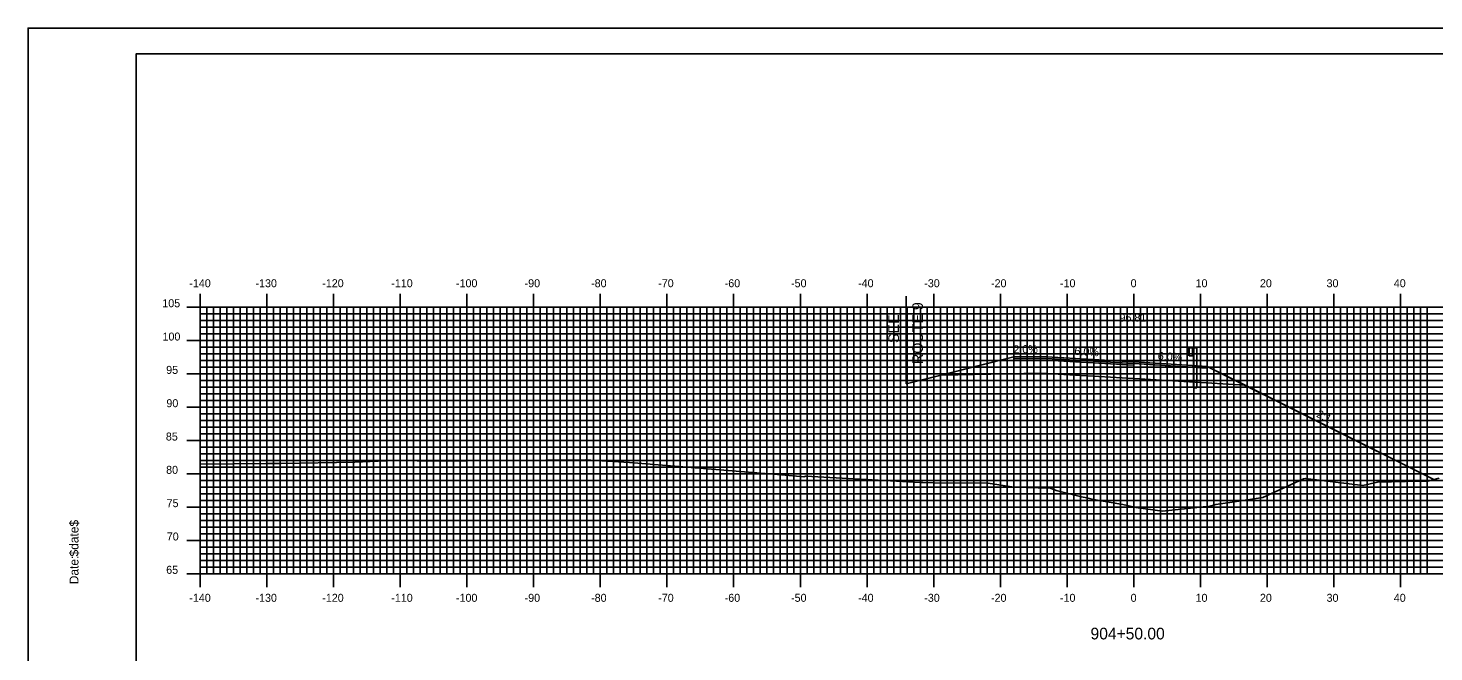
# Model space of a CAD drawing. Extents: x 857110 to 857453, y 364765 to 364985.
# Drawn here: x 857110 to 857320.8, y 364891.6 to 364985.2 of the extents above; entities that cross this region are included whole.
import ezdxf

# ---------------------------------------------------------------- set-up
doc = ezdxf.new("R2010")
doc.units = 0
for name, color, linetype in [('ANNOTATION', 7, 'Continuous'), ('BORDER', 7, 'Continuous'), ('D_Guardrail_Beam_Rt', 7, 'Continuous'), ('D_Roadway_Centerline', 7, 'Continuous'), ('D_Roadway_Centerline_Text', 7, 'Continuous'), ('D_Roadway_Edge_Shoulder', 7, 'Continuous'), ('D_Roadway_Edge_TW', 7, 'Continuous'), ('D_Roadway_Pavement', 7, 'Continuous'), ('D_Roadway_SlopeLines', 7, 'Continuous'), ('D_Roadway_SubGrade', 7, 'Continuous'), ('H_V ANNOTATION', 7, 'Continuous'), ('MAJOR', 7, 'Continuous'), ('MINOR', 7, 'Continuous'), ('PLOT BOUNDARY', 7, 'Continuous'), ('S_Roadway_Centerline', 7, 'Continuous')]:
    doc.layers.add(name, color=color, linetype=linetype)

msp = doc.modelspace()

# ---------------------------------------------------------------- linework, layer by layer
at = {"layer": 'BORDER'}
msp.add_lwpolyline([(857126.19, 364771.3), (857446.19, 364771.3), (857446.19, 364981.3), (857126.19, 364981.3)], close=True, dxfattribs=at)
at = {"layer": 'D_Guardrail_Beam_Rt'}
for p, q in [((857283.98, 364937.09), (857283.83, 364936.99)), ((857283.83, 364936.84), (857284.03, 364936.71)), ((857284.03, 364936.51), (857283.83, 364936.37)), ((857283.83, 364936.23), (857283.98, 364936.13)), ((857284.07, 364937.11), (857283.99, 364937.09)), ((857283.99, 364936.12), (857284.07, 364936.11)), ((857284.06, 364936.64), (857284.06, 364936.57)), ((857284.07, 364937.19), (857284.75, 364937.19)), ((857284.07, 364936.02), (857284.07, 364937.19)), ((857284.59, 364937.19), (857284.59, 364936.02)), ((857284.69, 364937.19), (857284.69, 364936.02)), ((857284.75, 364937.19), (857285.22, 364937.19)), ((857284.75, 364937.19), (857284.75, 364936.02)), ((857285.22, 364937.19), (857285.22, 364931.19)), ((857284.75, 364936.02), (857284.07, 364936.02)), ((857284.73, 364931.19), (857284.73, 364936.02)), ((857284.73, 364931.19), (857285.22, 364931.19))]:
    msp.add_line(p, q, dxfattribs=at)
for centre, major_axis, start_param, end_param in [((857283.88, 364936.91), (-0.0877, 0), 5.323254, 7.243116), ((857283.88, 364936.3), (-0.0877, 0), 5.323254, 7.243116), ((857284, 364937.05), (-0.0417, 0), 4.907132, 5.323254), ((857284, 364936.16), (-0.0417, 0), 0.959931, 1.376053), ((857283.98, 364936.64), (0.0789, 0), 0, 0.959931), ((857283.98, 364936.57), (0.0789, 0), 5.323254, 6.283185)]:
    msp.add_ellipse(centre, major_axis=major_axis, ratio=0.995501, start_param=start_param, end_param=end_param, dxfattribs=at)
at = {"layer": 'D_Roadway_Centerline'}
msp.add_lwpolyline([(857246.92, 364933.13), (857257.79, 364935.85), (857261.79, 364935.93), (857275.79, 364935.09), (857283.79, 364934.61), (857286.79, 364934.43), (857292.48, 364931.59), (857320.76, 364917.44)], dxfattribs=at)
at = {"layer": 'D_Roadway_Edge_Shoulder'}
for points in [[(857261.79, 364935.93), (857257.79, 364935.85), (857257.79, 364935.6), (857261.79, 364935.68)], [(857275.79, 364935.09), (857283.79, 364934.61), (857283.79, 364934.61), (857286.79, 364934.43), (857286.79, 364934.18), (857275.79, 364934.84)]]:
    msp.add_lwpolyline(points, close=True, dxfattribs=at)
at = {"layer": 'D_Roadway_Edge_TW'}
msp.add_lwpolyline([(857261.79, 364935.93), (857275.79, 364935.09), (857275.79, 364934.84), (857261.79, 364935.68)], close=True, dxfattribs=at)
at = {"layer": 'D_Roadway_Pavement'}
for points in [[(857261.79, 364935.68), (857257.79, 364935.6), (857257.79, 364935.35), (857261.79, 364935.43)], [(857261.79, 364935.68), (857275.79, 364934.84), (857275.79, 364934.59), (857261.79, 364935.43)]]:
    msp.add_lwpolyline(points, close=True, dxfattribs=at)
msp.add_lwpolyline([(857275.79, 364934.84), (857275.79, 364934.59)], dxfattribs=at)
msp.add_lwpolyline([(857275.79, 364934.84), (857275.79, 364934.59)], dxfattribs=at)
msp.add_lwpolyline([(857275.79, 364934.84), (857275.79, 364934.59)], dxfattribs=at)
at = {"layer": 'D_Roadway_SlopeLines'}
for points in [[(857286.79, 364934.43), (857320.76, 364917.44)], [(857241.65, 364931.81), (857246.92, 364933.13)]]:
    msp.add_lwpolyline(points, dxfattribs=at)
at = {"layer": 'D_Roadway_SubGrade'}
msp.add_line((857241.65, 364944.95), (857241.65, 364931.81), dxfattribs=at)
for points in [[(857261.79, 364935.43), (857257.79, 364935.35), (857257.79, 364935.6), (857257.79, 364935.85), (857246.92, 364933.13), (857261.79, 364933.43)], [(857261.79, 364935.43), (857275.79, 364934.59), (857275.79, 364932.59), (857261.79, 364933.43)], [(857275.79, 364934.59), (857275.79, 364934.84), (857286.79, 364934.18), (857286.79, 364934.43), (857292.48, 364931.59), (857275.79, 364932.59)]]:
    msp.add_lwpolyline(points, close=True, dxfattribs=at)
at = {"layer": 'MAJOR'}
for p, q in [((857135.79, 364945.31), (857135.79, 364943.3)), ((857145.79, 364945.31), (857145.79, 364943.3)), ((857155.79, 364945.31), (857155.79, 364943.3)), ((857165.79, 364945.31), (857165.79, 364943.3)), ((857175.79, 364945.31), (857175.79, 364943.3)), ((857185.79, 364945.31), (857185.79, 364943.3)), ((857195.79, 364945.31), (857195.79, 364943.3)), ((857205.79, 364945.31), (857205.79, 364943.3)), ((857215.79, 364945.31), (857215.79, 364943.3)), ((857225.79, 364945.31), (857225.79, 364943.3)), ((857235.79, 364945.31), (857235.79, 364943.3)), ((857245.79, 364945.31), (857245.79, 364943.3)), ((857255.79, 364945.31), (857255.79, 364943.3)), ((857265.79, 364945.31), (857265.79, 364943.3)), ((857275.79, 364945.31), (857275.79, 364943.3)), ((857285.79, 364945.31), (857285.79, 364943.3)), ((857295.79, 364945.31), (857295.79, 364943.3)), ((857305.79, 364945.31), (857305.79, 364943.3)), ((857315.79, 364945.31), (857315.79, 364943.3)), ((857133.79, 364943.3), (857135.79, 364943.3)), ((857135.79, 364943.3), (857415.79, 364943.3)), ((857135.79, 364903.3), (857135.79, 364943.3)), ((857135.79, 364903.3), (857135.79, 364943.3)), ((857135.79, 364943.3), (857415.79, 364943.3)), ((857145.79, 364903.3), (857145.79, 364943.3)), ((857155.79, 364903.3), (857155.79, 364943.3)), ((857165.79, 364903.3), (857165.79, 364943.3)), ((857175.79, 364903.3), (857175.79, 364943.3)), ((857185.79, 364903.3), (857185.79, 364943.3)), ((857195.79, 364903.3), (857195.79, 364943.3)), ((857205.79, 364903.3), (857205.79, 364943.3)), ((857215.79, 364903.3), (857215.79, 364943.3)), ((857225.79, 364903.3), (857225.79, 364943.3)), ((857235.79, 364903.3), (857235.79, 364943.3)), ((857245.79, 364903.3), (857245.79, 364943.3)), ((857255.79, 364903.3), (857255.79, 364943.3)), ((857265.79, 364903.3), (857265.79, 364943.3)), ((857275.79, 364903.3), (857275.79, 364943.3)), ((857285.79, 364903.3), (857285.79, 364943.3)), ((857295.79, 364903.3), (857295.79, 364943.3)), ((857305.79, 364903.3), (857305.79, 364943.3)), ((857315.79, 364903.3), (857315.79, 364943.3)), ((857133.79, 364938.3), (857135.79, 364938.3)), ((857135.79, 364938.3), (857415.79, 364938.3)), ((857133.79, 364933.3), (857135.79, 364933.3)), ((857135.79, 364933.3), (857415.79, 364933.3)), ((857133.79, 364928.3), (857135.79, 364928.3)), ((857135.79, 364928.3), (857415.79, 364928.3)), ((857133.79, 364923.3), (857135.79, 364923.3)), ((857135.79, 364923.3), (857415.79, 364923.3)), ((857133.79, 364918.3), (857135.79, 364918.3)), ((857135.79, 364918.3), (857415.79, 364918.3)), ((857133.79, 364913.3), (857135.79, 364913.3)), ((857135.79, 364913.3), (857415.79, 364913.3)), ((857133.79, 364908.3), (857135.79, 364908.3)), ((857135.79, 364908.3), (857415.79, 364908.3)), ((857133.79, 364903.3), (857135.79, 364903.3)), ((857135.79, 364903.3), (857415.79, 364903.3)), ((857135.79, 364903.3), (857415.79, 364903.3)), ((857135.79, 364901.3), (857135.79, 364903.3)), ((857145.79, 364901.3), (857145.79, 364903.3)), ((857155.79, 364901.3), (857155.79, 364903.3)), ((857165.79, 364901.3), (857165.79, 364903.3)), ((857175.79, 364901.3), (857175.79, 364903.3)), ((857185.79, 364901.3), (857185.79, 364903.3)), ((857195.79, 364901.3), (857195.79, 364903.3)), ((857205.79, 364901.3), (857205.79, 364903.3)), ((857215.79, 364901.3), (857215.79, 364903.3)), ((857225.79, 364901.3), (857225.79, 364903.3)), ((857235.79, 364901.3), (857235.79, 364903.3)), ((857245.79, 364901.3), (857245.79, 364903.3)), ((857255.79, 364901.3), (857255.79, 364903.3)), ((857265.79, 364901.3), (857265.79, 364903.3)), ((857275.79, 364901.3), (857275.79, 364903.3)), ((857285.79, 364901.3), (857285.79, 364903.3)), ((857295.79, 364901.3), (857295.79, 364903.3)), ((857305.79, 364901.3), (857305.79, 364903.3)), ((857315.79, 364901.3), (857315.79, 364903.3))]:
    msp.add_line(p, q, dxfattribs=at)
at = {"layer": 'MINOR'}
for p, q in [((857136.79, 364903.3), (857136.79, 364943.3)), ((857137.79, 364903.3), (857137.79, 364943.3)), ((857138.79, 364903.3), (857138.79, 364943.3)), ((857139.79, 364903.3), (857139.79, 364943.3)), ((857140.79, 364903.3), (857140.79, 364943.3)), ((857141.79, 364903.3), (857141.79, 364943.3)), ((857142.79, 364903.3), (857142.79, 364943.3)), ((857143.79, 364903.3), (857143.79, 364943.3)), ((857144.79, 364903.3), (857144.79, 364943.3)), ((857146.79, 364903.3), (857146.79, 364943.3)), ((857147.79, 364903.3), (857147.79, 364943.3)), ((857148.79, 364903.3), (857148.79, 364943.3)), ((857149.79, 364903.3), (857149.79, 364943.3)), ((857150.79, 364903.3), (857150.79, 364943.3)), ((857151.79, 364903.3), (857151.79, 364943.3)), ((857152.79, 364903.3), (857152.79, 364943.3)), ((857153.79, 364903.3), (857153.79, 364943.3)), ((857154.79, 364903.3), (857154.79, 364943.3)), ((857156.79, 364903.3), (857156.79, 364943.3)), ((857157.79, 364903.3), (857157.79, 364943.3)), ((857158.79, 364903.3), (857158.79, 364943.3)), ((857159.79, 364903.3), (857159.79, 364943.3)), ((857160.79, 364903.3), (857160.79, 364943.3)), ((857161.79, 364903.3), (857161.79, 364943.3)), ((857162.79, 364903.3), (857162.79, 364943.3)), ((857163.79, 364903.3), (857163.79, 364943.3)), ((857164.79, 364903.3), (857164.79, 364943.3)), ((857166.79, 364903.3), (857166.79, 364943.3)), ((857167.79, 364903.3), (857167.79, 364943.3)), ((857168.79, 364903.3), (857168.79, 364943.3)), ((857169.79, 364903.3), (857169.79, 364943.3)), ((857170.79, 364903.3), (857170.79, 364943.3)), ((857171.79, 364903.3), (857171.79, 364943.3)), ((857172.79, 364903.3), (857172.79, 364943.3)), ((857173.79, 364903.3), (857173.79, 364943.3)), ((857174.79, 364903.3), (857174.79, 364943.3)), ((857176.79, 364903.3), (857176.79, 364943.3)), ((857177.79, 364903.3), (857177.79, 364943.3)), ((857178.79, 364903.3), (857178.79, 364943.3)), ((857179.79, 364903.3), (857179.79, 364943.3)), ((857180.79, 364903.3), (857180.79, 364943.3)), ((857181.79, 364903.3), (857181.79, 364943.3)), ((857182.79, 364903.3), (857182.79, 364943.3)), ((857183.79, 364903.3), (857183.79, 364943.3)), ((857184.79, 364903.3), (857184.79, 364943.3)), ((857186.79, 364903.3), (857186.79, 364943.3)), ((857187.79, 364903.3), (857187.79, 364943.3)), ((857188.79, 364903.3), (857188.79, 364943.3)), ((857189.79, 364903.3), (857189.79, 364943.3)), ((857190.79, 364903.3), (857190.79, 364943.3)), ((857191.79, 364903.3), (857191.79, 364943.3)), ((857192.79, 364903.3), (857192.79, 364943.3)), ((857193.79, 364903.3), (857193.79, 364943.3)), ((857194.79, 364903.3), (857194.79, 364943.3)), ((857196.79, 364903.3), (857196.79, 364943.3)), ((857197.79, 364903.3), (857197.79, 364943.3)), ((857198.79, 364903.3), (857198.79, 364943.3)), ((857199.79, 364903.3), (857199.79, 364943.3)), ((857200.79, 364903.3), (857200.79, 364943.3)), ((857201.79, 364903.3), (857201.79, 364943.3)), ((857202.79, 364903.3), (857202.79, 364943.3)), ((857203.79, 364903.3), (857203.79, 364943.3)), ((857204.79, 364903.3), (857204.79, 364943.3)), ((857206.79, 364903.3), (857206.79, 364943.3)), ((857207.79, 364903.3), (857207.79, 364943.3)), ((857208.79, 364903.3), (857208.79, 364943.3)), ((857209.79, 364903.3), (857209.79, 364943.3)), ((857210.79, 364903.3), (857210.79, 364943.3)), ((857211.79, 364903.3), (857211.79, 364943.3)), ((857212.79, 364903.3), (857212.79, 364943.3)), ((857213.79, 364903.3), (857213.79, 364943.3)), ((857214.79, 364903.3), (857214.79, 364943.3)), ((857216.79, 364903.3), (857216.79, 364943.3)), ((857217.79, 364903.3), (857217.79, 364943.3)), ((857218.79, 364903.3), (857218.79, 364943.3)), ((857219.79, 364903.3), (857219.79, 364943.3)), ((857220.79, 364903.3), (857220.79, 364943.3)), ((857221.79, 364903.3), (857221.79, 364943.3)), ((857222.79, 364903.3), (857222.79, 364943.3)), ((857223.79, 364903.3), (857223.79, 364943.3)), ((857224.79, 364903.3), (857224.79, 364943.3)), ((857226.79, 364903.3), (857226.79, 364943.3)), ((857227.79, 364903.3), (857227.79, 364943.3)), ((857228.79, 364903.3), (857228.79, 364943.3)), ((857229.79, 364903.3), (857229.79, 364943.3)), ((857230.79, 364903.3), (857230.79, 364943.3)), ((857231.79, 364903.3), (857231.79, 364943.3)), ((857232.79, 364903.3), (857232.79, 364943.3)), ((857233.79, 364903.3), (857233.79, 364943.3)), ((857234.79, 364903.3), (857234.79, 364943.3)), ((857236.79, 364903.3), (857236.79, 364943.3)), ((857237.79, 364903.3), (857237.79, 364943.3)), ((857238.79, 364903.3), (857238.79, 364943.3)), ((857239.79, 364903.3), (857239.79, 364943.3)), ((857240.79, 364903.3), (857240.79, 364943.3)), ((857241.79, 364903.3), (857241.79, 364943.3)), ((857242.79, 364903.3), (857242.79, 364943.3)), ((857243.79, 364903.3), (857243.79, 364943.3)), ((857244.79, 364903.3), (857244.79, 364943.3)), ((857246.79, 364903.3), (857246.79, 364943.3)), ((857247.79, 364903.3), (857247.79, 364943.3)), ((857248.79, 364903.3), (857248.79, 364943.3)), ((857249.79, 364903.3), (857249.79, 364943.3)), ((857250.79, 364903.3), (857250.79, 364943.3)), ((857251.79, 364903.3), (857251.79, 364943.3)), ((857252.79, 364903.3), (857252.79, 364943.3)), ((857253.79, 364903.3), (857253.79, 364943.3)), ((857254.79, 364903.3), (857254.79, 364943.3)), ((857256.79, 364903.3), (857256.79, 364943.3)), ((857257.79, 364903.3), (857257.79, 364943.3)), ((857258.79, 364903.3), (857258.79, 364943.3)), ((857259.79, 364903.3), (857259.79, 364943.3)), ((857260.79, 364903.3), (857260.79, 364943.3)), ((857261.79, 364903.3), (857261.79, 364943.3)), ((857262.79, 364903.3), (857262.79, 364943.3)), ((857263.79, 364903.3), (857263.79, 364943.3)), ((857264.79, 364903.3), (857264.79, 364943.3)), ((857266.79, 364903.3), (857266.79, 364943.3)), ((857267.79, 364903.3), (857267.79, 364943.3)), ((857268.79, 364903.3), (857268.79, 364943.3)), ((857269.79, 364903.3), (857269.79, 364943.3)), ((857270.79, 364903.3), (857270.79, 364943.3)), ((857271.79, 364903.3), (857271.79, 364943.3)), ((857272.79, 364903.3), (857272.79, 364943.3)), ((857273.79, 364903.3), (857273.79, 364943.3)), ((857274.79, 364903.3), (857274.79, 364943.3)), ((857276.79, 364903.3), (857276.79, 364943.3)), ((857277.79, 364903.3), (857277.79, 364943.3)), ((857278.79, 364903.3), (857278.79, 364943.3)), ((857279.79, 364903.3), (857279.79, 364943.3)), ((857280.79, 364903.3), (857280.79, 364943.3)), ((857281.79, 364903.3), (857281.79, 364943.3)), ((857282.79, 364903.3), (857282.79, 364943.3)), ((857283.79, 364903.3), (857283.79, 364943.3)), ((857284.79, 364903.3), (857284.79, 364943.3)), ((857286.79, 364903.3), (857286.79, 364943.3)), ((857287.79, 364903.3), (857287.79, 364943.3)), ((857288.79, 364903.3), (857288.79, 364943.3)), ((857289.79, 364903.3), (857289.79, 364943.3)), ((857290.79, 364903.3), (857290.79, 364943.3)), ((857291.79, 364903.3), (857291.79, 364943.3)), ((857292.79, 364903.3), (857292.79, 364943.3)), ((857293.79, 364903.3), (857293.79, 364943.3)), ((857294.79, 364903.3), (857294.79, 364943.3)), ((857296.79, 364903.3), (857296.79, 364943.3)), ((857297.79, 364903.3), (857297.79, 364943.3)), ((857298.79, 364903.3), (857298.79, 364943.3)), ((857299.79, 364903.3), (857299.79, 364943.3)), ((857300.79, 364903.3), (857300.79, 364943.3)), ((857301.79, 364903.3), (857301.79, 364943.3)), ((857302.79, 364903.3), (857302.79, 364943.3)), ((857303.79, 364903.3), (857303.79, 364943.3)), ((857304.79, 364903.3), (857304.79, 364943.3)), ((857306.79, 364903.3), (857306.79, 364943.3)), ((857307.79, 364903.3), (857307.79, 364943.3)), ((857308.79, 364903.3), (857308.79, 364943.3)), ((857309.79, 364903.3), (857309.79, 364943.3)), ((857310.79, 364903.3), (857310.79, 364943.3)), ((857311.79, 364903.3), (857311.79, 364943.3)), ((857312.79, 364903.3), (857312.79, 364943.3)), ((857313.79, 364903.3), (857313.79, 364943.3)), ((857314.79, 364903.3), (857314.79, 364943.3)), ((857316.79, 364903.3), (857316.79, 364943.3)), ((857317.79, 364903.3), (857317.79, 364943.3)), ((857318.79, 364903.3), (857318.79, 364943.3)), ((857319.79, 364903.3), (857319.79, 364943.3)), ((857135.79, 364942.3), (857415.79, 364942.3)), ((857135.79, 364942.3), (857137.8, 364942.3)), ((857135.79, 364941.3), (857415.79, 364941.3)), ((857135.79, 364941.3), (857137.8, 364941.3)), ((857135.79, 364940.3), (857415.79, 364940.3)), ((857135.79, 364940.3), (857137.8, 364940.3)), ((857135.79, 364939.3), (857415.79, 364939.3)), ((857135.79, 364939.3), (857137.8, 364939.3)), ((857135.79, 364937.3), (857415.79, 364937.3)), ((857135.79, 364937.3), (857137.8, 364937.3)), ((857135.79, 364936.3), (857415.79, 364936.3)), ((857135.79, 364936.3), (857137.8, 364936.3)), ((857135.79, 364935.3), (857415.79, 364935.3)), ((857135.79, 364935.3), (857137.8, 364935.3)), ((857135.79, 364934.3), (857415.79, 364934.3)), ((857135.79, 364934.3), (857137.8, 364934.3)), ((857257.79, 364935.85), (857241.65, 364931.81)), ((857135.79, 364932.3), (857415.79, 364932.3)), ((857135.79, 364932.3), (857137.8, 364932.3)), ((857135.79, 364931.3), (857415.79, 364931.3)), ((857135.79, 364931.3), (857137.8, 364931.3)), ((857135.79, 364930.3), (857415.79, 364930.3)), ((857135.79, 364930.3), (857137.8, 364930.3)), ((857135.79, 364929.3), (857415.79, 364929.3)), ((857135.79, 364929.3), (857137.8, 364929.3)), ((857135.79, 364927.3), (857415.79, 364927.3)), ((857135.79, 364927.3), (857137.8, 364927.3)), ((857135.79, 364926.3), (857415.79, 364926.3)), ((857135.79, 364926.3), (857137.8, 364926.3)), ((857135.79, 364925.3), (857415.79, 364925.3)), ((857135.79, 364925.3), (857137.8, 364925.3)), ((857135.79, 364924.3), (857415.79, 364924.3)), ((857135.79, 364924.3), (857137.8, 364924.3)), ((857135.79, 364922.3), (857415.79, 364922.3)), ((857135.79, 364922.3), (857137.8, 364922.3)), ((857135.79, 364921.3), (857415.79, 364921.3)), ((857135.79, 364921.3), (857137.8, 364921.3)), ((857135.79, 364920.3), (857415.79, 364920.3)), ((857135.79, 364920.3), (857137.8, 364920.3)), ((857135.79, 364919.3), (857415.79, 364919.3)), ((857135.79, 364919.3), (857137.8, 364919.3)), ((857135.79, 364917.3), (857415.79, 364917.3)), ((857135.79, 364917.3), (857137.8, 364917.3)), ((857135.79, 364916.3), (857415.79, 364916.3)), ((857135.79, 364916.3), (857137.8, 364916.3)), ((857135.79, 364915.3), (857415.79, 364915.3)), ((857135.79, 364915.3), (857137.8, 364915.3)), ((857135.79, 364914.3), (857415.79, 364914.3)), ((857135.79, 364914.3), (857137.8, 364914.3)), ((857135.79, 364912.3), (857415.79, 364912.3)), ((857135.79, 364912.3), (857137.8, 364912.3)), ((857135.79, 364911.3), (857415.79, 364911.3)), ((857135.79, 364911.3), (857137.8, 364911.3)), ((857135.79, 364910.3), (857415.79, 364910.3)), ((857135.79, 364910.3), (857137.8, 364910.3)), ((857135.79, 364909.3), (857415.79, 364909.3)), ((857135.79, 364909.3), (857137.8, 364909.3)), ((857135.79, 364907.3), (857415.79, 364907.3)), ((857135.79, 364907.3), (857137.8, 364907.3)), ((857135.79, 364906.3), (857415.79, 364906.3)), ((857135.79, 364906.3), (857137.8, 364906.3)), ((857135.79, 364905.3), (857415.79, 364905.3)), ((857135.79, 364905.3), (857137.8, 364905.3)), ((857135.79, 364904.3), (857415.79, 364904.3)), ((857135.79, 364904.3), (857137.8, 364904.3))]:
    msp.add_line(p, q, dxfattribs=at)
at = {"layer": 'PLOT BOUNDARY'}
msp.add_lwpolyline([(857110.01, 364765.18), (857450.01, 364765.18), (857450.01, 364985.18), (857110.01, 364985.18)], close=True, dxfattribs=at)
at = {"layer": 'S_Roadway_Centerline'}
msp.add_lwpolyline([(857135.79, 364919.73), (857145.67, 364919.85), (857147.96, 364919.84), (857158.98, 364920.05), (857164.8, 364920.28), (857166.72, 364920.32), (857169.88, 364920.18), (857193.53, 364920.4), (857200.19, 364920.01), (857222.97, 364918.13), (857226.3, 364917.87), (857226.46, 364917.89), (857226.62, 364917.93), (857242.01, 364917.08), (857243.69, 364916.99), (857244.18, 364916.98), (857245.72, 364916.93), (857253.95, 364916.9), (857257.78, 364916.3), (857263.31, 364916.17), (857264.17, 364915.8), (857267.94, 364914.84), (857268.75, 364914.68), (857269.75, 364914.43), (857274.15, 364913.68), (857276.11, 364913.26), (857280.09, 364912.72), (857286.19, 364913.36), (857287.03, 364913.42), (857288.09, 364913.68), (857290.56, 364914.06), (857295.14, 364914.76), (857301.21, 364917.53), (857301.53, 364917.61), (857310.13, 364916.55), (857312.33, 364917.04), (857318.63, 364917.19), (857319.86, 364917.2), (857321.59, 364917.66)], dxfattribs=at)

# ---------------------------------------------------------------- texts
at = {"layer": 'ANNOTATION'}
for s, height, rotation, p in [('ROUTE 9', 1.6, 90, (857244.18, 364934.78)), ('SEE', 1.6, 90, (857240.58, 364937.93)), ('2.0%', 1.2, 1.1458, (857257.75, 364936.38)), ('6.0%', 1.2, 356.5664, (857266.86, 364936.16)), ('6.0%', 1.2, 356.5664, (857279.36, 364935.41)), ('2:1', 1.2, 333.4349, (857303.06, 364926.89))]:
    msp.add_text(s, height=height, rotation=rotation, dxfattribs=at).set_placement(p)
at = {"layer": 'BORDER'}
for s, p in [('$date$', (857117.56, 364905.91)), ('Date:', (857117.56, 364901.74))]:
    msp.add_text(s, height=1.339, rotation=90, dxfattribs=at).set_placement(p)
at = {"layer": 'D_Roadway_Centerline_Text'}
msp.add_text('96.81', height=1.2, dxfattribs=at).set_placement((857273.64, 364941.15))
at = {"layer": 'H_V ANNOTATION'}
for s, height, p in [('-140', 1.2, (857134.18, 364946.3)), ('-130', 1.2, (857144.1, 364946.3)), ('-120', 1.2, (857154.11, 364946.3)), ('-110', 1.2, (857164.46, 364946.3)), ('-100', 1.2, (857174.16, 364946.3)), ('-90', 1.2, (857184.45, 364946.3)), ('-80', 1.2, (857194.42, 364946.3)), ('-70', 1.2, (857204.48, 364946.3)), ('-60', 1.2, (857214.45, 364946.3)), ('-50', 1.2, (857224.4, 364946.3)), ('-40', 1.2, (857234.45, 364946.3)), ('-30', 1.2, (857244.37, 364946.3)), ('-20', 1.2, (857254.38, 364946.3)), ('-10', 1.2, (857264.72, 364946.3)), ('0', 1.2, (857275.31, 364946.3)), ('10', 1.2, (857285.05, 364946.3)), ('20', 1.2, (857294.7, 364946.3)), ('30', 1.2, (857304.69, 364946.3)), ('40', 1.2, (857314.77, 364946.3)), ('105', 1.2, (857130.13, 364943.3)), ('100', 1.2, (857130.16, 364938.3)), ('95', 1.2, (857130.71, 364933.3)), ('90', 1.2, (857130.74, 364928.3)), ('85', 1.2, (857130.66, 364923.3)), ('80', 1.2, (857130.7, 364918.3)), ('75', 1.2, (857130.77, 364913.3)), ('70', 1.2, (857130.8, 364908.3)), ('65', 1.2, (857130.71, 364903.3)), ('-140', 1.2, (857134.18, 364899.1)), ('-130', 1.2, (857144.1, 364899.1)), ('-120', 1.2, (857154.11, 364899.1)), ('-110', 1.2, (857164.46, 364899.1)), ('-100', 1.2, (857174.16, 364899.1)), ('-90', 1.2, (857184.45, 364899.1)), ('-80', 1.2, (857194.42, 364899.1)), ('-70', 1.2, (857204.48, 364899.1)), ('-60', 1.2, (857214.45, 364899.1)), ('-50', 1.2, (857224.4, 364899.1)), ('-40', 1.2, (857234.45, 364899.1)), ('-30', 1.2, (857244.37, 364899.1)), ('-20', 1.2, (857254.38, 364899.1)), ('-10', 1.2, (857264.72, 364899.1)), ('0', 1.2, (857275.31, 364899.1)), ('10', 1.2, (857285.05, 364899.1)), ('20', 1.2, (857294.7, 364899.1)), ('30', 1.2, (857304.69, 364899.1)), ('40', 1.2, (857314.77, 364899.1)), ('904+50.00', 1.75, (857269.3, 364893.46))]:
    msp.add_text(s, height=height, dxfattribs=at).set_placement(p)
at = {"layer": 'MAJOR'}
msp.add_text('-', height=0.012, dxfattribs=at).set_placement((857135.79, 364903.3))

doc.saveas('drawing.dxf')
